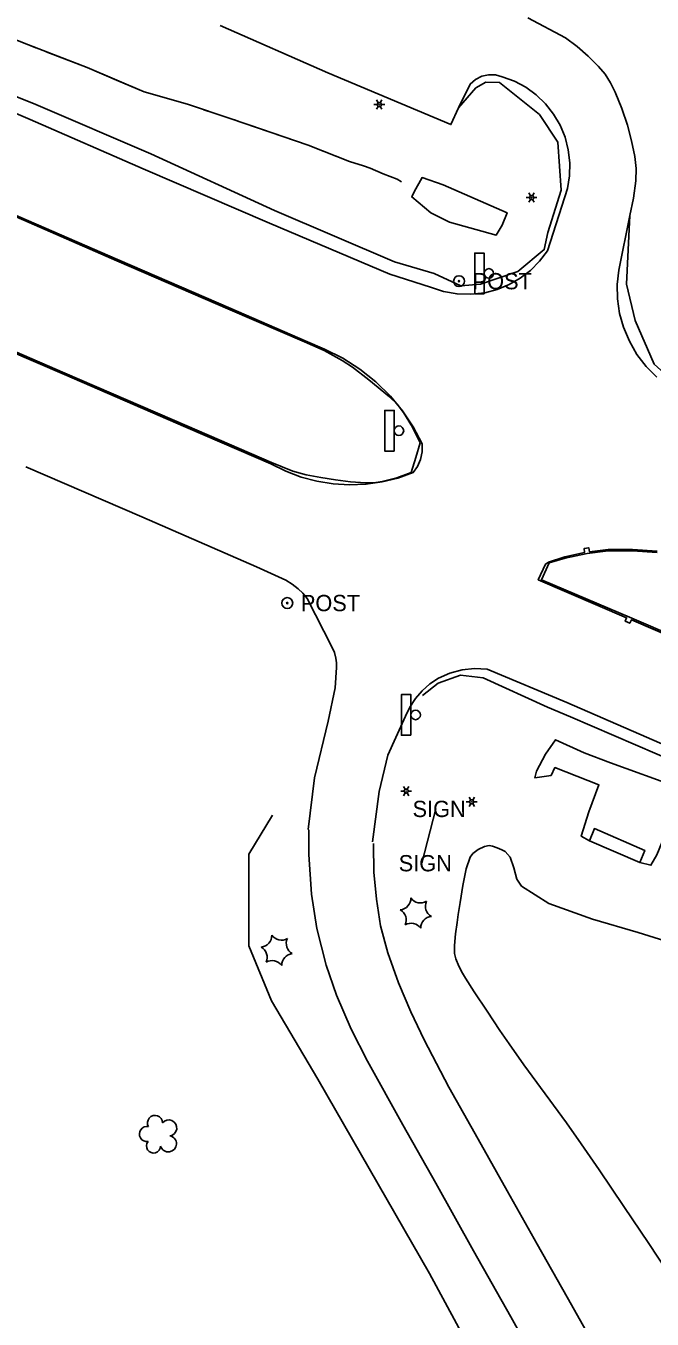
# Model space of a CAD drawing. Extents: x 588843 to 2552415, y 180129 to 269402.
# Drawn here: x 592421.6 to 592652.5, y 185814.8 to 186291.4 of the extents above; entities that cross this region are included whole.
import ezdxf

# ---------------------------------------------------------------- set-up
doc = ezdxf.new("R2010")
doc.units = 0
for name, color, linetype in [('E_DRN_RipRap', 7, 'Continuous'), ('E_LTG', 7, 'Continuous'), ('E_MISCPROP', 7, 'Continuous'), ('E_MISCPROP_YardLight', 7, 'Continuous'), ('E_RDWY', 7, 'Continuous'), ('E_RDWY_AsphConc', 7, 'Continuous'), ('E_RDWY_C_and_G', 7, 'Continuous'), ('E_RDWY_Gravel', 7, 'Continuous'), ('E_SGN', 7, 'Continuous'), ('E_WTR_Wetland', 7, 'Continuous'), ('Level 11', 7, 'Continuous'), ('Level 17', 7, 'Continuous'), ('Level 18', 7, 'Continuous'), ('Level 19', 7, 'Continuous')]:
    doc.layers.add(name, color=color, linetype=linetype)

# ---------------------------------------------------------------- blocks, each defined once
blk = doc.blocks.new('BSGN')
at = {"layer": 'E_SGN'}
blk.add_text('SIGN', height=12, dxfattribs=at).set_placement((-17.11, -6))
blk = doc.blocks.new('LPOL_2')
at = {"layer": 'E_LTG'}
for p, q in [((-4, 0), (-1.5, 0)), ((-0.75, 1.3), (-2, 3.46)), ((0.75, 1.3), (2, 3.46)), ((1.5, 0), (4, 0)), ((-2, -3.46), (-0.75, -1.3)), ((2, -3.46), (0.75, -1.3))]:
    blk.add_line(p, q, dxfattribs=at)
for radius in [1.5, 1.5, 1.5, 0.125]:
    blk.add_circle((0, 0), radius, dxfattribs=at)
blk = doc.blocks.new('POST')
at = {"layer": 'E_MISCPROP'}
for radius in [4, 0.5]:
    blk.add_circle((0, 0), radius, dxfattribs=at)
blk.add_text('POST', height=12, dxfattribs=at).set_placement((10, -6))
blk = doc.blocks.new('SGN')
at = {"layer": 'E_SGN'}
blk.add_lwpolyline([(-3.5, -15), (-10.5, -15), (-10.5, 15), (-3.5, 15)], close=True, dxfattribs=at)
blk.add_circle((0, 0), 3.5, dxfattribs=at)

msp = doc.modelspace()

# ---------------------------------------------------------------- linework, layer by layer
at = {"layer": 'E_DRN_RipRap'}
for points in [[(592577.74, 186219), (592570.91, 186222.51), (592563.86, 186228.34), (592564.82, 186230.28), (592567.66, 186235.46), (592575.4, 186232.78), (592599.01, 186222.55), (592597.23, 186217.9), (592594.96, 186214.26)], [(592629.38, 185991.01), (592626.33, 185992.8), (592629.12, 186001.75), (592632.89, 186011.64), (592616.68, 186018.04), (592615.28, 186015.17), (592609.25, 186014.27), (592609.84, 186016.69), (592613.26, 186022.99), (592616.85, 186028.28), (592627.5, 186023.53), (592637.11, 186019.78), (592661.58, 186010.99), (592659.06, 186003.85), (592658.23, 185995.42), (592654.28, 185985.85), (592652.06, 185982.02), (592647.94, 185983.04)]]:
    msp.add_lwpolyline(points, close=True, dxfattribs=at)
at = {"layer": 'E_RDWY'}
for points in [[(592379.3, 186275.53), (592423.17, 186256.92), (592464.87, 186238.67), (592511.47, 186218.74), (592555.79, 186199.91), (592570.74, 186195.08), (592575.59, 186193.5), (592580.61, 186192.63), (592585.71, 186192.49), (592590.77, 186193.07), (592590.77, 186193.07), (592595.37, 186194.26), (592599.77, 186196.05), (592603.9, 186198.41), (592607.67, 186201.29), (592611.03, 186204.66), (592613.91, 186208.43), (592613.91, 186208.43), (592613.91, 186208.43), (592621.3, 186231.42), (592622.07, 186236.15), (592622.18, 186240.95), (592621.62, 186245.72), (592620.41, 186250.37), (592620.41, 186250.37), (592618.59, 186254.78), (592616.18, 186258.9), (592613.22, 186262.65), (592609.78, 186265.95), (592605.92, 186268.76), (592601.71, 186271.01), (592597.22, 186272.66), (592597.22, 186272.66), (592597.22, 186272.66), (592594.76, 186273.33), (592592.2, 186273.39), (592589.71, 186272.83), (592589.71, 186272.83), (592587.38, 186271.67), (592585.4, 186269.97), (592585.4, 186269.97), (592581.17, 186261.22), (592578.33, 186255.01), (592532.98, 186274.14), (592493.18, 186291.52)], [(592606.72, 186294.41), (592620.55, 186286.94), (592624.89, 186283.77), (592628.97, 186280.27), (592632.77, 186276.45), (592632.77, 186276.45), (592635.16, 186273.55), (592637.21, 186270.39), (592638.89, 186267.03), (592638.89, 186267.03), (592641.31, 186260.96), (592643.38, 186254.76), (592643.38, 186254.76), (592644.92, 186249.07), (592646.1, 186243.3), (592646.1, 186243.3), (592646.59, 186238.8), (592646.5, 186234.28), (592646.5, 186234.28), (592645.67, 186227.85), (592644.28, 186221.52), (592644.28, 186221.52), (592640.22, 186201.42), (592639.67, 186196.1), (592639.78, 186190.75), (592640.55, 186185.45), (592641.97, 186180.3), (592641.97, 186180.3), (592644.12, 186175.14), (592646.91, 186170.3), (592650.3, 186165.86), (592654.23, 186161.9)], [(592410.21, 186224.81), (592455.41, 186205.28), (592497.17, 186187.22), (592524.61, 186175.37)], [(592392.59, 186181.52), (592435.76, 186162.87), (592480.61, 186143.47), (592511.96, 186129.96), (592517.38, 186127.26), (592523.04, 186125.12), (592528.88, 186123.55), (592534.86, 186122.58), (592540.9, 186122.22), (592546.95, 186122.46), (592546.95, 186122.46), (592546.95, 186122.46), (592552.91, 186123.31), (592558.77, 186124.75), (592564.45, 186126.77), (592564.45, 186126.77), (592566.04, 186129.02), (592567.15, 186131.54), (592567.15, 186131.54), (592567.75, 186134.44), (592567.71, 186137.4), (592567.71, 186137.4), (592564.39, 186143.62), (592560.47, 186149.48), (592555.99, 186154.92), (592555.99, 186154.92), (592550.65, 186160.2), (592544.79, 186164.88), (592538.46, 186168.92), (592531.74, 186172.27), (592531.74, 186172.27), (592524.61, 186175.37)], [(592421.54, 186128.89), (592464.35, 186110.41), (592506.66, 186092.03), (592517.47, 186087.11), (592519.82, 186085.66), (592521.98, 186083.96), (592521.98, 186083.96), (592523.71, 186082.26), (592525.25, 186080.39), (592525.25, 186080.39), (592534.53, 186062.3), (592535.4, 186060.41), (592535.94, 186058.39), (592535.94, 186058.39), (592536.13, 186056.66), (592536.07, 186054.92), (592536.07, 186054.92), (592535.59, 186047.46), (592532.99, 186035.12), (592528.02, 186014.27), (592525.71, 185995.16)], [(592694.59, 186051.17), (592644.88, 186072.55), (592644.3, 186071.24), (592642.58, 186071.94), (592643.08, 186073.26), (592610.55, 186087.25), (592613.14, 186093.05), (592614.29, 186093.72), (592620.36, 186095.73), (592627.58, 186097.29), (592627.41, 186098.72), (592629.15, 186099.05), (592629.4, 186097.6), (592636.26, 186098.36), (592645.34, 186098.36), (592654.4, 186097.81)], [(592549.46, 185990.67), (592551.82, 186009.2), (592555.02, 186022.6), (592561.6, 186036.93), (592563.22, 186040.34), (592565.28, 186043.5), (592567.75, 186046.35), (592570.58, 186048.85), (592573.72, 186050.93), (592573.72, 186050.93), (592577.95, 186052.89), (592582.44, 186054.12), (592587.07, 186054.58), (592591.71, 186054.26), (592591.71, 186054.26), (592621.01, 186041.99), (592663.72, 186023.42)]]:
    msp.add_lwpolyline(points, dxfattribs=at)
at = {"layer": 'E_RDWY_AsphConc'}
msp.add_lwpolyline([(592629.38, 185991.01), (592631.24, 185995.54), (592649.83, 185987.53), (592647.94, 185983.04)], close=True, dxfattribs=at)
at = {"layer": 'E_RDWY_C_and_G'}
for points in [[(592410, 186224.4), (592455.14, 186204.8), (592496.87, 186186.76), (592524.35, 186174.92)], [(592392.79, 186182.04), (592435.9, 186163.35), (592480.87, 186143.94), (592512.2, 186130.43), (592520.08, 186127.31), (592520.08, 186127.31), (592524.95, 186125.94), (592524.95, 186125.94), (592530.36, 186124.89), (592535.8, 186124.04), (592535.8, 186124.04), (592541.32, 186123.38), (592546.86, 186122.93), (592546.86, 186122.93), (592549.94, 186122.96), (592552.97, 186123.43), (592552.97, 186123.43), (592558.37, 186124.88), (592563.63, 186126.76), (592563.63, 186126.76), (592565.4, 186132.32), (592566.95, 186137.75), (592564.11, 186143.45), (592560.81, 186148.91), (592560.81, 186148.91), (592558.46, 186151.95), (592555.72, 186154.65), (592555.72, 186154.65), (592548.04, 186161), (592548.04, 186161), (592541.98, 186165.64), (592541.98, 186165.64), (592538.26, 186168.08), (592538.26, 186168.08), (592531.61, 186171.74), (592531.61, 186171.74), (592524.35, 186174.92)], [(592694.79, 186051.67), (592644.19, 186073.46), (592611.67, 186087.26), (592614.54, 186093.44), (592620.45, 186095.18), (592628.62, 186096.9), (592636.31, 186097.9), (592645.34, 186097.88), (592654.36, 186097.31)]]:
    msp.add_lwpolyline(points, dxfattribs=at)
at = {"layer": 'E_RDWY_Gravel'}
for points in [[(592380.84, 186280.24), (592425.26, 186262.47), (592467.66, 186244.18), (592513.32, 186223.34), (592557.5, 186204.41), (592572.15, 186200.12), (592581.99, 186195.58), (592589.23, 186196.21), (592603, 186200.9), (592612.74, 186208.96), (592614.01, 186215.27), (592618.99, 186230.86), (592617.7, 186248.48), (592610.99, 186258.73), (592596.26, 186270.54), (592591.19, 186270.71), (592587.54, 186268.55), (592581.17, 186261.22)], [(592644.28, 186221.52), (592643.07, 186196.23), (592646.24, 186182.77), (592653.3, 186166.77), (592660.55, 186160.2), (592681.92, 186150.3), (592723.97, 186131.5), (592739.95, 186124.33), (592770.95, 186110.67), (592820.92, 186089.89), (592865.89, 186070.74), (592910.48, 186053.88), (592930.92, 186044.32), (592944.15, 186039.98), (592954.56, 186034.59), (592997.98, 186014.46), (593007.63, 186009.96)], [(592567.83, 186044.62), (592573.57, 186049.09), (592581.8, 186052.09), (592590.22, 186051.09), (592613.93, 186040.31), (592622.42, 186036.74), (592662.37, 186019.58), (592706.76, 185999.77), (592748.12, 185980.45), (592792.8, 185961.89), (592839.2, 185941.36), (592876.07, 185924.75), (592914.61, 185908.27), (592919.58, 185904.44), (592922.45, 185898.38), (592927.2, 185890.53), (592927.43, 185880.43)]]:
    msp.add_lwpolyline(points, dxfattribs=at)
at = {"layer": 'E_SGN'}
msp.add_lwpolyline([(592567.62, 185982.79), (592572.73, 186002.8)], dxfattribs=at)
at = {"layer": 'E_WTR_Wetland'}
msp.add_lwpolyline([(592657.66, 185832.9), (592651.25, 185842.59), (592642.13, 185856.24), (592632.95, 185869.84), (592626.36, 185879.41), (592620.9, 185887.06), (592613.07, 185897.79), (592605.25, 185908.53), (592599.82, 185916.19), (592596.41, 185921.17), (592591.65, 185928.24), (592586.93, 185935.35), (592583.69, 185940.43), (592582.64, 185942.25), (592581.27, 185944.87), (592580.09, 185947.54), (592579.61, 185949.54), (592579.62, 185952.52), (592580.06, 185956.71), (592580.63, 185960.9), (592581.05, 185963.87), (592581.73, 185968.31), (592582.75, 185974.57), (592583.99, 185980.76), (592585.36, 185984.99), (592586.43, 185986.39), (592588.43, 185987.82), (592590.66, 185988.92), (592592.4, 185989.28), (592593.68, 185989.06), (592595.4, 185988.43), (592597.11, 185987.68), (592598.31, 185987.13), (592600.23, 185985.06), (592601.5, 185981.11), (592602.67, 185976.92), (592604.31, 185974.36), (592614.46, 185967.92), (592630.57, 185962.18), (592647.36, 185957.29), (592659.19, 185953.56)], dxfattribs=at)
at = {"layer": 'Level 11'}
for points in [[(592626.06, 185768.95), (592614.86, 185789.48), (592600.37, 185815.55), (592586.66, 185839.95), (592572.72, 185864.92), (592560.55, 185886.4), (592547.6, 185909.83), (592541.5, 185921.68), (592536.08, 185934.21), (592532.27, 185945.24), (592528.9, 185958.77), (592526.85, 185971.35), (592525.92, 185985.96), (592525.92, 185995.12)], [(592549.78, 185990.1), (592549.75, 185989.72), (592549.87, 185979.52), (592550.83, 185969.5), (592552.34, 185959.72), (592555.02, 185949.78), (592558.94, 185938.66), (592563.59, 185927.98), (592568.43, 185917.74), (592577.5, 185900.27), (592588.33, 185881.08), (592599.11, 185862.03), (592610.15, 185842.39), (592621.19, 185822.83), (592629.46, 185808.19), (592635.87, 185796.45), (592642.78, 185783.39), (592649.48, 185769.93)]]:
    msp.add_lwpolyline(points, dxfattribs=at)
at = {"layer": 'Level 17'}
msp.add_lwpolyline([(592632.26, 185711.18), (592607.66, 185762.6), (592570.46, 185831.58), (592529.22, 185903.16), (592512.19, 185932.08), (592503.85, 185952.33), (592503.85, 185986.12), (592512.53, 186000.47)], dxfattribs=at)
at = {"layer": 'Level 18'}
for centre, radius, start, end in [((592559.26, 185969.9), 4.3, 275.2113, 0.9762), ((592567.07, 185972.45), 4.3, 215.2113, 300.9762), ((592573.19, 185966.96), 4.3, 155.2113, 240.9762), ((592557.56, 185961.86), 4.3, 335.2113, 60.9762), ((592571.5, 185958.92), 4.3, 95.2113, 180.9762), ((592563.68, 185956.37), 4.3, 35.2113, 120.9762), ((592507.98, 185956.16), 4.3, 275.2113, 0.9762), ((592515.79, 185958.71), 4.3, 215.2113, 300.9762), ((592521.91, 185953.22), 4.3, 155.2113, 240.9762), ((592506.28, 185948.11), 4.3, 335.2113, 60.9762), ((592520.22, 185945.18), 4.3, 95.2113, 180.9762), ((592512.4, 185942.62), 4.3, 35.2113, 120.9762), ((592466.2, 185882.99), 2.78, 78.0716, 279.0826), ((592469.2, 185887.07), 2.78, 1.3946, 209.1675), ((592474.24, 185885.21), 2.97, 278.4237, 139.6575), ((592474.13, 185879.36), 2.97, 196.0745, 79.0477), ((592468.66, 185878.59), 2.61, 140.7797, 358.7123)]:
    msp.add_arc(centre, radius, start, end, dxfattribs=at)
at = {"layer": 'Level 19'}
for points in [[(592404.9, 186291.29), (592422.59, 186284.38), (592444.19, 186276), (592465.25, 186267.1), (592481.13, 186262.5), (592497.34, 186257.12), (592525.73, 186247.43), (592540.97, 186241.46), (592546.07, 186239.81), (592548.58, 186238.92), (592553.29, 186236.82), (592558.45, 186234.86), (592560.09, 186233.94)], [(592423.43, 186284.06), (592425.29, 186283.33)], [(592429.02, 186281.89), (592444.19, 186276), (592455.91, 186271.05)], [(592455.91, 186271.05), (592465.25, 186267.1), (592481.13, 186262.5), (592483.34, 186261.77)], [(592487.14, 186260.51), (592489.04, 186259.88)], [(592492.83, 186258.62), (592494.73, 186257.99)], [(592498.53, 186256.72), (592500.42, 186256.07)], [(592504.2, 186254.78), (592525.73, 186247.43), (592531.55, 186245.15)], [(592531.55, 186245.15), (592540.97, 186241.46), (592546.07, 186239.81), (592548.58, 186238.92), (592553.29, 186236.82), (592558.45, 186234.86), (592558.61, 186234.77)]]:
    msp.add_lwpolyline(points, dxfattribs=at)

# ---------------------------------------------------------------- block references
at = {"layer": 'E_LTG', "xscale": 0.5, "yscale": 0.5}
for p in [(592551.9, 186262.39), (592608.06, 186228.11)]:
    msp.add_blockref('LPOL_2', p, dxfattribs=at)
at = {"layer": 'E_MISCPROP', "xscale": 0.5, "yscale": 0.5}
for p in [(592581.33, 186197.31), (592517.98, 186078.68)]:
    msp.add_blockref('POST', p, dxfattribs=at)
at = {"layer": 'E_MISCPROP_YardLight', "xscale": 0.5, "yscale": 0.5}
for p in [(592561.82, 186009.37), (592585.99, 186005.41)]:
    msp.add_blockref('LPOL_2', p, dxfattribs=at)
at = {"layer": 'E_SGN', "xscale": 0.5, "yscale": 0.5}
for name, p in [('SGN', (592592.33, 186200.17)), ('SGN', (592559.15, 186142.2)), ('SGN', (592565.31, 186037.44)), ('BSGN', (592572.73, 186002.8)), ('BSGN', (592567.62, 185982.79))]:
    msp.add_blockref(name, p, dxfattribs=at)

doc.saveas('drawing.dxf')
